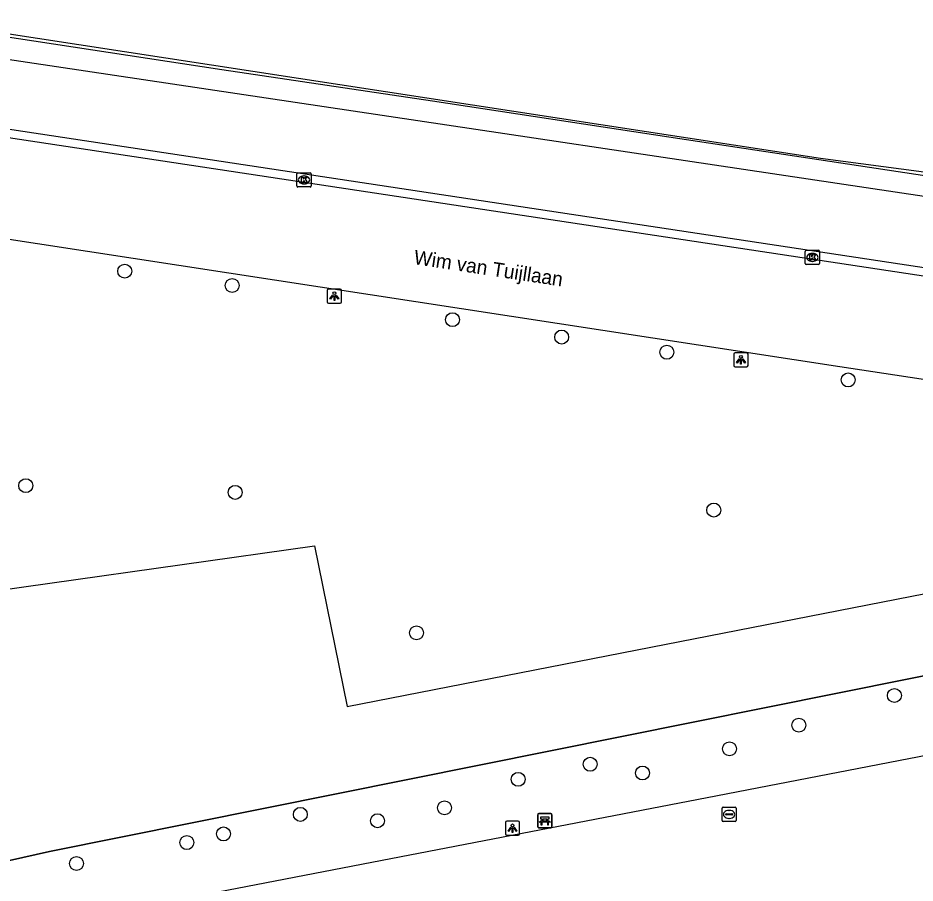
# Model space of a CAD drawing. Extents: x 160203 to 161526, y 379529 to 381797.
# Drawn here: x 160853.7 to 160916.7, y 380497.8 to 380558.5 of the extents above; entities that cross this region are included whole.
import ezdxf

# ---------------------------------------------------------------- set-up
doc = ezdxf.new("R2010")
doc.units = 0
for name, color, linetype in [('IMGEO_Bank', 7, 'Continuous'), ('IMGEO_Boom', 7, 'Continuous'), ('IMGEO_Gemengd_bos', 7, 'Continuous'), ('IMGEO_Hek', 7, 'Continuous'), ('IMGEO_Kolk', 7, 'Continuous'), ('IMGEO_Lichtpunt', 7, 'Continuous'), ('IMGEO_Loofbos', 7, 'Continuous'), ('IMGEO_Openbare_ruimte_label', 7, 'Continuous'), ('IMGEO_Parkeervlak_gesloten', 7, 'Continuous'), ('IMGEO_Rijbaan_lokaal_open', 7, 'Continuous'), ('IMGEO_Waterleidingput', 7, 'Continuous')]:
    doc.layers.add(name, color=color, linetype=linetype)

msp = doc.modelspace()

# ---------------------------------------------------------------- linework, layer by layer
at = {"layer": 'IMGEO_Bank'}
for p, q in [((160890.207, 380501.737), (160890.207, 380502.578)), ((160890.207, 380502.578), (160890.207, 380501.737)), ((160890.282, 380502.662), (160891.123, 380502.662)), ((160891.123, 380502.662), (160890.282, 380502.662)), ((160890.516, 380502.168), (160890.516, 380502.274)), ((160890.56, 380502.274), (160890.56, 380502.168)), ((160890.848, 380502.28), (160890.566, 380502.28)), ((160890.854, 380502.168), (160890.854, 380502.274)), ((160890.898, 380502.274), (160890.898, 380502.168)), ((160891.207, 380502.587), (160891.207, 380501.746)), ((160891.207, 380501.746), (160891.207, 380502.587)), ((160891.132, 380501.662), (160890.291, 380501.662)), ((160890.291, 380501.662), (160891.132, 380501.662)), ((160890.904, 380502.06), (160890.511, 380502.06)), ((160890.566, 380502.162), (160890.848, 380502.162))]:
    msp.add_line(p, q, dxfattribs=at)
for points in [[(160890.51, 380502.28), (160890.424, 380502.28), (160890.424, 380502.441), (160890.987, 380502.441), (160890.987, 380502.28), (160890.904, 380502.28)], [(160890.454, 380502.06), (160890.312, 380502.06), (160890.424, 380502.162), (160890.51, 380502.162)], [(160890.504, 380502.053), (160890.504, 380501.846), (160890.461, 380501.846), (160890.461, 380502.053)], [(160890.904, 380502.162), (160890.987, 380502.162), (160891.099, 380502.06), (160890.96, 380502.06)], [(160890.954, 380502.053), (160890.954, 380501.846), (160890.91, 380501.846), (160890.91, 380502.053)]]:
    msp.add_lwpolyline(points, dxfattribs=at)
for centre, radius, start, end in [((160890.285, 380502.584), 0.0779, 92.4484, 184.28452), ((160890.285, 380502.584), 0.0779, 92.4484, 184.28452), ((160890.509, 380502.273), 0.00671, 2.89567, 87.10433), ((160890.566, 380502.273), 0.00671, 92.89567, 177.10433), ((160890.848, 380502.273), 0.00671, 2.89567, 87.10433), ((160890.905, 380502.273), 0.00671, 92.89567, 177.10433), ((160891.129, 380502.584), 0.0779, 2.4484, 94.28452), ((160891.129, 380502.584), 0.0779, 2.4484, 94.28452), ((160890.285, 380501.74), 0.0779, 182.4484, 274.28452), ((160890.285, 380501.74), 0.0779, 182.4484, 274.28452), ((160890.454, 380502.053), 0.00671, 2.89567, 87.10433), ((160890.511, 380502.053), 0.00671, 92.89567, 177.10433), ((160890.509, 380502.169), 0.00671, 272.89567, 357.10433), ((160890.566, 380502.169), 0.00671, 182.89567, 267.10433), ((160890.848, 380502.169), 0.00671, 272.89567, 357.10433), ((160890.905, 380502.169), 0.00671, 182.89567, 267.10433), ((160890.903, 380502.053), 0.00671, 2.89567, 87.10433), ((160890.96, 380502.053), 0.00671, 92.89567, 177.10433), ((160891.129, 380501.74), 0.0779, 272.4484, 4.28452), ((160891.129, 380501.74), 0.0779, 272.4484, 4.28452)]:
    msp.add_arc(centre, radius, start, end, dxfattribs=at)
at = {"layer": 'IMGEO_Boom'}
for centre in [(160861.201, 380540.743), (160868.746, 380539.739), (160884.22, 380537.341), (160891.893, 380536.122), (160899.274, 380535.055), (160912.016, 380533.112), (160854.25, 380525.69), (160868.965, 380525.217), (160902.573, 380523.976), (160881.696, 380515.353), (160915.261, 380510.954), (160908.554, 380508.875), (160903.682, 380507.213), (160893.893, 380506.126), (160888.836, 380505.071), (160897.566, 380505.513), (160883.658, 380503.063), (160873.538, 380502.608), (160878.951, 380502.162), (160868.136, 380501.236), (160865.56, 380500.628), (160857.809, 380499.164)]:
    msp.add_circle(centre, 0.489, dxfattribs=at)
at = {"layer": 'IMGEO_Gemengd_bos'}
msp.add_lwpolyline([(160845.74, 380558.527), (160910.065, 380548.671), (160940.334, 380544.69)], dxfattribs=at)
at = {"layer": 'IMGEO_Hek'}
for points in [[(160964.899, 380552.777), (160964.896, 380551.38), (160959.504, 380551), (160940.157, 380543.996), (160899.412, 380550.147), (160882.829, 380552.68), (160868.014, 380554.875), (160845.741, 380558.276)], [(160951.518, 380519.182), (160951.456, 380519.19), (160855.926, 380500)], [(160855.926, 380500), (160832.145, 380494.674)]]:
    msp.add_lwpolyline(points, dxfattribs=at)
at = {"layer": 'IMGEO_Kolk'}
for p, q in [((160873.369, 380547.658), (160874.221, 380547.658)), ((160873.294, 380546.732), (160873.294, 380547.584)), ((160873.782, 380547.438), (160873.807, 380547.438)), ((160874.295, 380547.584), (160874.295, 380546.732)), ((160874.221, 380546.658), (160873.369, 380546.658)), ((160873.805, 380546.878), (160873.78, 380546.878)), ((160909, 380541.288), (160909, 380542.14)), ((160909.075, 380542.214), (160909.927, 380542.214)), ((160909.488, 380541.994), (160909.513, 380541.994)), ((160910.001, 380542.14), (160910.001, 380541.288)), ((160909.511, 380541.434), (160909.486, 380541.434)), ((160909.927, 380541.214), (160909.075, 380541.214))]:
    msp.add_line(p, q, dxfattribs=at)
for points in [[(160873.369, 380547.658), (160874.221, 380547.658)], [(160873.294, 380546.732), (160873.294, 380547.584)], [(160873.615, 380547.358), (160873.738, 380547.358), (160873.738, 380547.207), (160873.868, 380547.358), (160874.032, 380547.358), (160873.886, 380547.207), (160874.039, 380546.958), (160873.887, 380546.958), (160873.802, 380547.122), (160873.738, 380547.055), (160873.738, 380546.958), (160873.615, 380546.958), (160873.615, 380547.358)], [(160874.295, 380547.584), (160874.295, 380546.732)], [(160874.221, 380546.658), (160873.369, 380546.658)], [(160909, 380541.288), (160909, 380542.14)], [(160909.075, 380542.214), (160909.927, 380542.214)], [(160910.001, 380542.14), (160910.001, 380541.288)], [(160909.321, 380541.914), (160909.444, 380541.914), (160909.444, 380541.763), (160909.574, 380541.914), (160909.738, 380541.914), (160909.592, 380541.763), (160909.745, 380541.514), (160909.593, 380541.514), (160909.508, 380541.678), (160909.444, 380541.611), (160909.444, 380541.514), (160909.321, 380541.514), (160909.321, 380541.914)], [(160909.927, 380541.214), (160909.075, 380541.214)]]:
    msp.add_lwpolyline(points, dxfattribs=at)
for centre, start, end in [((160873.371, 380547.582), 91.55205, 178.44795), ((160873.371, 380547.582), 91.55205, 178.44795), ((160874.219, 380547.582), 1.55205, 88.44795), ((160874.219, 380547.582), 1.55205, 88.44795), ((160873.371, 380546.734), 181.55205, 268.44795), ((160873.371, 380546.734), 181.55205, 268.44795), ((160874.219, 380546.734), 271.55205, 358.44795), ((160874.219, 380546.734), 271.55205, 358.44795), ((160909.077, 380542.138), 91.55205, 178.44795), ((160909.077, 380542.138), 91.55205, 178.44795), ((160909.925, 380542.138), 1.55205, 88.44795), ((160909.925, 380542.138), 1.55205, 88.44795), ((160909.077, 380541.29), 181.55205, 268.44795), ((160909.077, 380541.29), 181.55205, 268.44795), ((160909.925, 380541.29), 271.55205, 358.44795), ((160909.925, 380541.29), 271.55205, 358.44795)]:
    msp.add_arc(centre, 0.0765, start, end, dxfattribs=at)
for centre, major_axis, ratio, start_param, end_param in [((160873.781, 380547.158), (-0.387, 0.002), 0.722429, 4.712389, 7.853982), ((160873.806, 380547.158), (-0.39, 0.002), 0.717154, 1.570796, 4.712389), ((160909.487, 380541.714), (-0.387, 0.002), 0.722429, 4.712389, 7.853982), ((160909.512, 380541.714), (-0.39, 0.002), 0.717154, 1.570796, 4.712389)]:
    msp.add_ellipse(centre, major_axis=major_axis, ratio=ratio, start_param=start_param, end_param=end_param, dxfattribs=at)
at = {"layer": 'IMGEO_Lichtpunt'}
for p, q in [((160876.33, 380539.495), (160875.522, 380539.495)), ((160876.33, 380539.495), (160875.522, 380539.495)), ((160875.428, 380539.4), (160875.428, 380538.593)), ((160875.428, 380539.4), (160875.428, 380538.593)), ((160876.424, 380538.593), (160876.424, 380539.4)), ((160876.424, 380538.593), (160876.424, 380539.4)), ((160875.522, 380538.499), (160876.33, 380538.499)), ((160875.522, 380538.499), (160876.33, 380538.499)), ((160903.985, 380534.926), (160903.985, 380534.119)), ((160903.985, 380534.926), (160903.985, 380534.119)), ((160904.887, 380535.021), (160904.079, 380535.021)), ((160904.887, 380535.021), (160904.079, 380535.021)), ((160904.981, 380534.119), (160904.981, 380534.926)), ((160904.981, 380534.119), (160904.981, 380534.926)), ((160904.079, 380534.025), (160904.887, 380534.025)), ((160904.079, 380534.025), (160904.887, 380534.025)), ((160887.939, 380502.04), (160887.939, 380501.233)), ((160887.939, 380502.04), (160887.939, 380501.233)), ((160888.841, 380502.135), (160888.033, 380502.135)), ((160888.841, 380502.135), (160888.033, 380502.135)), ((160888.935, 380501.233), (160888.935, 380502.04)), ((160888.935, 380501.233), (160888.935, 380502.04)), ((160888.033, 380501.139), (160888.841, 380501.139)), ((160888.033, 380501.139), (160888.841, 380501.139))]:
    msp.add_line(p, q, dxfattribs=at)
for points in [[(160875.802, 380539.064), (160875.841, 380539.036), (160875.653, 380538.774), (160875.615, 380538.801), (160875.802, 380539.064)], [(160875.904, 380539.016), (160875.951, 380539.016), (160875.951, 380538.694), (160875.904, 380538.694), (160875.904, 380539.016)], [(160876.014, 380539.036), (160876.052, 380539.063), (160876.239, 380538.801), (160876.2, 380538.773), (160876.014, 380539.036)], [(160904.359, 380534.59), (160904.398, 380534.562), (160904.21, 380534.3), (160904.172, 380534.327), (160904.359, 380534.59)], [(160904.461, 380534.542), (160904.508, 380534.542), (160904.508, 380534.22), (160904.461, 380534.22), (160904.461, 380534.542)], [(160904.571, 380534.562), (160904.609, 380534.589), (160904.796, 380534.327), (160904.757, 380534.299), (160904.571, 380534.562)], [(160888.313, 380501.704), (160888.352, 380501.676), (160888.164, 380501.414), (160888.126, 380501.441), (160888.313, 380501.704)], [(160888.415, 380501.656), (160888.462, 380501.656), (160888.462, 380501.334), (160888.415, 380501.334), (160888.415, 380501.656)], [(160888.525, 380501.676), (160888.563, 380501.703), (160888.75, 380501.441), (160888.711, 380501.413), (160888.525, 380501.676)]]:
    msp.add_lwpolyline(points, dxfattribs=at)
for centre in [(160875.927, 380539.198), (160904.484, 380534.724), (160888.438, 380501.838)]:
    msp.add_circle(centre, 0.0994, dxfattribs=at)
for centre, start, end in [((160875.522, 380539.4), 90, 180), ((160875.522, 380539.4), 90, 180), ((160876.33, 380539.4), 0, 90), ((160876.33, 380539.4), 0, 90), ((160875.522, 380538.593), 180, 270), ((160875.522, 380538.593), 180, 270), ((160876.33, 380538.593), 270, 0), ((160876.33, 380538.593), 270, 360), ((160904.079, 380534.926), 90, 180), ((160904.079, 380534.926), 90, 180), ((160904.887, 380534.926), 0, 90), ((160904.887, 380534.926), 0, 90), ((160904.079, 380534.119), 180, 270), ((160904.079, 380534.119), 180, 270), ((160904.887, 380534.119), 270, 0), ((160904.887, 380534.119), 270, 360), ((160888.033, 380502.04), 90, 180), ((160888.033, 380502.04), 90, 180), ((160888.841, 380502.04), 0, 90), ((160888.841, 380502.04), 0, 90), ((160888.033, 380501.233), 180, 270), ((160888.033, 380501.233), 180, 270), ((160888.841, 380501.233), 270, 0), ((160888.841, 380501.233), 270, 360)]:
    msp.add_arc(centre, 0.0946, start, end, dxfattribs=at)
at = {"layer": 'IMGEO_Loofbos'}
for points in [[(160832.145, 380494.674), (160831.064, 380500), (160828.037, 380514.908), (160874.529, 380521.462), (160876.82, 380510.174), (160917.453, 380518.109), (160923.009, 380526.579), (160955.011, 380521.483), (160954.687, 380518.782)], [(160832.145, 380494.674), (160855.926, 380500), (160951.456, 380519.19), (160951.518, 380519.182), (160951.934, 380519.13)], [(160863.045, 380342.63), (160833.499, 380489.33), (160833.56, 380489.783), (160833.852, 380490.316), (160834.2, 380490.611), (160834.638, 380490.788), (160879.901, 380499.518), (160902.101, 380503.8), (160944.615, 380512.001), (160946.869, 380502.452)]]:
    msp.add_lwpolyline(points, dxfattribs=at)
at = {"layer": 'IMGEO_Parkeervlak_gesloten'}
msp.add_lwpolyline([(160940.686, 380542.511), (160845.744, 380556.692)], dxfattribs=at)
at = {"layer": 'IMGEO_Rijbaan_lokaal_open'}
for points in [[(160828.18, 380554.482), (161000, 380528.513), (161026.173, 380524.441)], [(160828.089, 380553.895), (161000, 380527.913), (161026.094, 380523.879)], [(160965.031, 380525.91), (160911.436, 380534.021), (160831.991, 380546.196), (160825.841, 380547.097)]]:
    msp.add_lwpolyline(points, dxfattribs=at)
at = {"layer": 'IMGEO_Waterleidingput'}
for p, q in [((160903.153, 380502.184), (160903.153, 380503.036)), ((160903.228, 380503.11), (160904.08, 380503.11)), ((160904.154, 380503.036), (160904.154, 380502.184)), ((160903.412, 380502.604), (160903.412, 380502.616)), ((160903.85, 380502.567), (160903.452, 380502.567)), ((160903.455, 380502.653), (160903.853, 380502.653)), ((160903.664, 380502.33), (160903.639, 380502.33)), ((160903.641, 380502.89), (160903.666, 380502.89)), ((160903.896, 380502.616), (160903.896, 380502.604)), ((160904.08, 380502.11), (160903.228, 380502.11))]:
    msp.add_line(p, q, dxfattribs=at)
for points in [[(160903.153, 380502.184), (160903.153, 380503.036)], [(160903.228, 380503.11), (160904.08, 380503.11)], [(160904.154, 380503.036), (160904.154, 380502.184)], [(160904.08, 380502.11), (160903.228, 380502.11)]]:
    msp.add_lwpolyline(points, dxfattribs=at)
for centre, radius, start, end in [((160903.23, 380503.034), 0.0765, 91.55205, 178.44795), ((160903.23, 380503.034), 0.0765, 91.55205, 178.44795), ((160904.078, 380503.034), 0.0765, 1.55205, 88.44795), ((160904.078, 380503.034), 0.0765, 1.55205, 88.44795), ((160903.452, 380502.613), 0.0403, 85.87752, 175.75265), ((160903.449, 380502.603), 0.0366, 178.93798, 274.71019), ((160903.853, 380502.61), 0.043, 264.86636, 352.45326), ((160903.857, 380502.615), 0.0386, 1.73085, 96.63898), ((160903.23, 380502.186), 0.0765, 181.55205, 268.44795), ((160903.23, 380502.186), 0.0765, 181.55205, 268.44795), ((160904.078, 380502.186), 0.0765, 271.55205, 358.44795), ((160904.078, 380502.186), 0.0765, 271.55205, 358.44795)]:
    msp.add_arc(centre, radius, start, end, dxfattribs=at)
for centre, major_axis, ratio, start_param, end_param in [((160903.64, 380502.61), (-0.387, 0.002), 0.722429, 4.712389, 7.853982), ((160903.665, 380502.61), (-0.39, 0.002), 0.717154, 1.570796, 4.712389)]:
    msp.add_ellipse(centre, major_axis=major_axis, ratio=ratio, start_param=start_param, end_param=end_param, dxfattribs=at)

# ---------------------------------------------------------------- texts
at = {"layer": 'IMGEO_Openbare_ruimte_label'}
msp.add_text('Wim van Tuijllaan', height=1, rotation=351.37577, dxfattribs=at).set_placement((160881.46, 380541.253))

doc.saveas('drawing.dxf')
